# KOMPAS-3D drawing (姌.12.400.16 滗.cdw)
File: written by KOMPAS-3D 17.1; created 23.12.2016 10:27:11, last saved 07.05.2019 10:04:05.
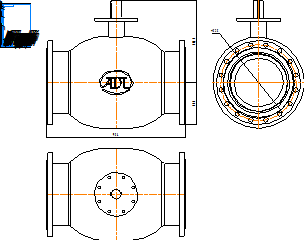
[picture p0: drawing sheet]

Sheet 1: A4, portrait

Title block, sheet 1: name: КШ.12.400.16 фф; material: Внимание! Данный продукт является объектом авторского права ООО «Торговый Дом АДЛ». / Запрещается изменение, копирование, распространение / (в том числе путем копирования на другие сайты и ресурсы в Интернете) / или любое иное использование информации и объектов без предварительного / согласия правообладателя (ООО «Торговый Дом АДЛ»).; sheets: 1; organisation: ООО "Торговый дом АДЛ"; sheet format: A4; stored path: C:\Users\tra\Desktop\2д чертежи\Шаровые краны БИВАЛ\КШ_Бивал_серия_11_12\KOMPAS_2D\КШ.12.400.16 фф.cdw

Views: Вид 1, Проекционный вид 2, Проекционный вид 3
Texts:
  Klimkovich
  ADL
Dimensions and other numbers on the sheet: 956; 564,5; 290; 525; 1:1; 1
